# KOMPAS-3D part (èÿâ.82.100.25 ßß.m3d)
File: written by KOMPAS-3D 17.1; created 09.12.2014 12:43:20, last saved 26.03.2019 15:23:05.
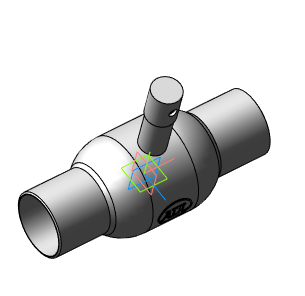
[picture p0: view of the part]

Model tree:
1. Операция без истории:8  (labels: Сталь 20  ГОСТ 1050-88)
